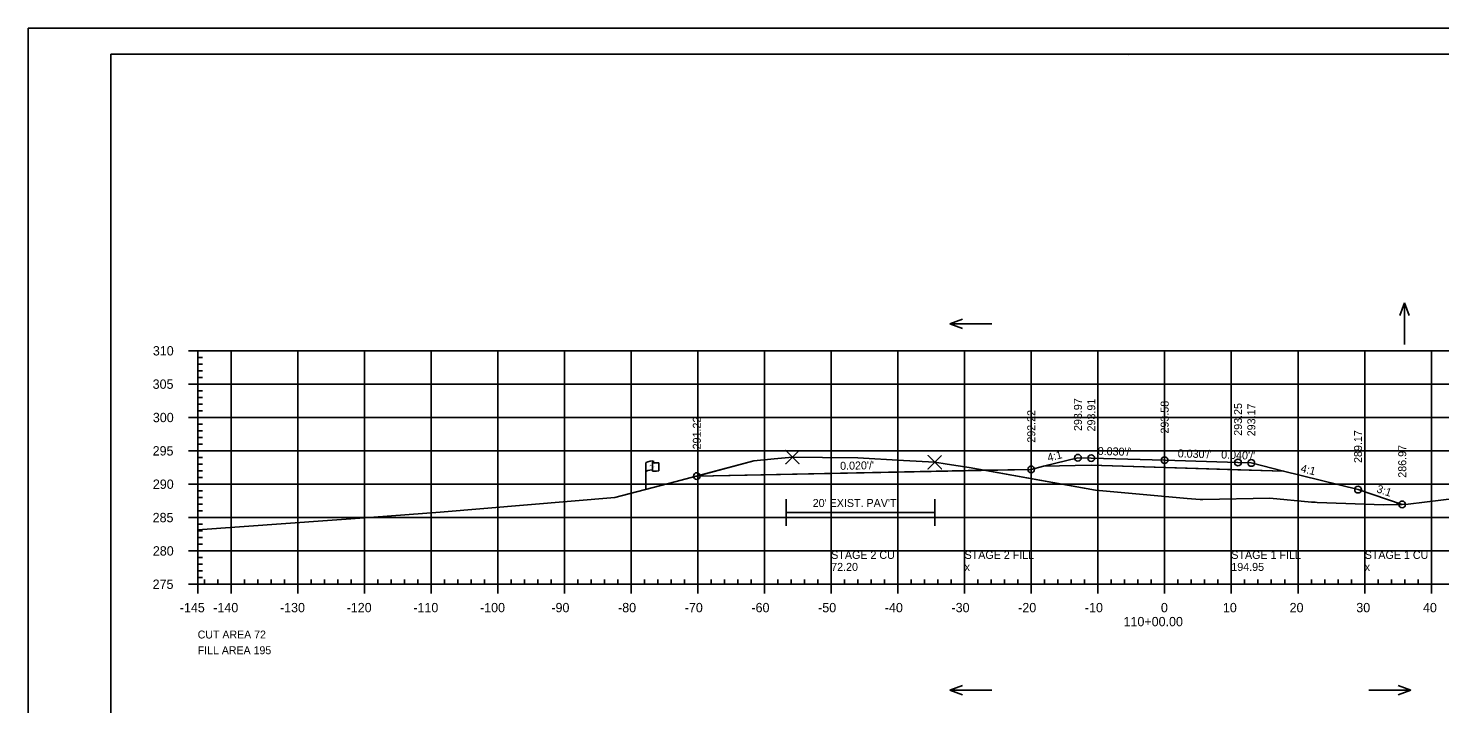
# Model space of a CAD drawing. Extents: x 1370843 to 1371177, y 380307 to 382654.
# Drawn here: x 1370843.3 to 1371055, y 381059.5 to 381160.8 of the extents above; entities that cross this region are included whole.
import ezdxf

# ---------------------------------------------------------------- set-up
doc = ezdxf.new("R2010")
doc.units = 0
for name, color, linetype in [('R_Alt Surface', 7, 'Continuous'), ('R_Axis', 7, 'Continuous'), ('R_Axis Annot', 7, 'Continuous'), ('R_Border', 7, 'Continuous'), ('R_Border Notes', 7, 'Continuous'), ('R_Exist Surface', 7, 'Continuous'), ('R_Exist Surface Annot', 7, 'Continuous'), ('R_Fin Surface', 7, 'Continuous'), ('R_Fin Surface Annot', 7, 'Continuous'), ('R_Grid', 7, 'Continuous'), ('R_No Plot', 7, 'Continuous'), ('R_ROW', 7, 'Continuous'), ('R_Water Annot', 7, 'Continuous')]:
    doc.layers.add(name, color=color, linetype=linetype)

msp = doc.modelspace()

# ---------------------------------------------------------------- linework, layer by layer
at = {"layer": 'R_Alt Surface'}
msp.add_lwpolyline([(1370995.56, 381095.15), (1371002.71, 381095.29), (1371013.71, 381094.96), (1371024.71, 381094.63), (1371031.54, 381094.43)], dxfattribs=at)
at = {"layer": 'R_Axis'}
for p, q in [((1370867.31, 381112.46), (1370868.71, 381112.46)), ((1370868.71, 381077.46), (1370868.71, 381112.46)), ((1370868.71, 381111.46), (1370869.41, 381111.46)), ((1370868.71, 381110.46), (1370869.41, 381110.46)), ((1370868.71, 381109.46), (1370869.41, 381109.46)), ((1370868.71, 381108.46), (1370869.41, 381108.46)), ((1370867.31, 381107.46), (1370868.71, 381107.46)), ((1370868.71, 381106.46), (1370869.41, 381106.46)), ((1370868.71, 381105.46), (1370869.41, 381105.46)), ((1370868.71, 381104.46), (1370869.41, 381104.46)), ((1370867.31, 381102.46), (1370868.71, 381102.46)), ((1370868.71, 381103.46), (1370869.41, 381103.46)), ((1370868.71, 381101.46), (1370869.41, 381101.46)), ((1370868.71, 381100.46), (1370869.41, 381100.46)), ((1370867.31, 381097.46), (1370868.71, 381097.46)), ((1370868.71, 381099.46), (1370869.41, 381099.46)), ((1370868.71, 381098.46), (1370869.41, 381098.46)), ((1370868.71, 381096.46), (1370869.41, 381096.46)), ((1370868.71, 381095.46), (1370869.41, 381095.46)), ((1370868.71, 381094.46), (1370869.41, 381094.46)), ((1370868.71, 381093.46), (1370869.41, 381093.46)), ((1370867.31, 381092.46), (1370868.71, 381092.46)), ((1370868.71, 381091.46), (1370869.41, 381091.46)), ((1370868.71, 381090.46), (1370869.41, 381090.46)), ((1370868.71, 381089.46), (1370869.41, 381089.46)), ((1370867.31, 381087.46), (1370868.71, 381087.46)), ((1370868.71, 381088.46), (1370869.41, 381088.46)), ((1370868.71, 381086.46), (1370869.41, 381086.46)), ((1370868.71, 381085.46), (1370869.41, 381085.46)), ((1370868.71, 381084.46), (1370869.41, 381084.46)), ((1370868.71, 381083.46), (1370869.41, 381083.46)), ((1370867.31, 381082.46), (1370868.71, 381082.46)), ((1370868.71, 381081.46), (1370869.41, 381081.46)), ((1370868.71, 381080.46), (1370869.41, 381080.46)), ((1370868.71, 381079.46), (1370869.41, 381079.46)), ((1370868.71, 381078.46), (1370869.41, 381078.46)), ((1370867.31, 381077.46), (1370868.71, 381077.46)), ((1370868.71, 381077.46), (1370868.71, 381078.16)), ((1370868.71, 381077.46), (1371158.71, 381077.46)), ((1370868.71, 381076.06), (1370868.71, 381077.46)), ((1370869.71, 381077.46), (1370869.71, 381078.16)), ((1370871.71, 381077.46), (1370871.71, 381078.16)), ((1370873.71, 381076.06), (1370873.71, 381077.46)), ((1370875.71, 381077.46), (1370875.71, 381078.16)), ((1370877.71, 381077.46), (1370877.71, 381078.16)), ((1370879.71, 381077.46), (1370879.71, 381078.16)), ((1370881.71, 381077.46), (1370881.71, 381078.16)), ((1370883.71, 381076.06), (1370883.71, 381077.46)), ((1370885.71, 381077.46), (1370885.71, 381078.16)), ((1370887.71, 381077.46), (1370887.71, 381078.16)), ((1370889.71, 381077.46), (1370889.71, 381078.16)), ((1370891.71, 381077.46), (1370891.71, 381078.16)), ((1370893.71, 381076.06), (1370893.71, 381077.46)), ((1370895.71, 381077.46), (1370895.71, 381078.16)), ((1370897.71, 381077.46), (1370897.71, 381078.16)), ((1370899.71, 381077.46), (1370899.71, 381078.16)), ((1370901.71, 381077.46), (1370901.71, 381078.16)), ((1370903.71, 381076.06), (1370903.71, 381077.46)), ((1370905.71, 381077.46), (1370905.71, 381078.16)), ((1370907.71, 381077.46), (1370907.71, 381078.16)), ((1370909.71, 381077.46), (1370909.71, 381078.16)), ((1370911.71, 381077.46), (1370911.71, 381078.16)), ((1370913.71, 381076.06), (1370913.71, 381077.46)), ((1370915.71, 381077.46), (1370915.71, 381078.16)), ((1370917.71, 381077.46), (1370917.71, 381078.16)), ((1370919.71, 381077.46), (1370919.71, 381078.16)), ((1370921.71, 381077.46), (1370921.71, 381078.16)), ((1370923.71, 381076.06), (1370923.71, 381077.46)), ((1370925.71, 381077.46), (1370925.71, 381078.16)), ((1370927.71, 381077.46), (1370927.71, 381078.16)), ((1370929.71, 381077.46), (1370929.71, 381078.16)), ((1370931.71, 381077.46), (1370931.71, 381078.16)), ((1370933.71, 381076.06), (1370933.71, 381077.46)), ((1370935.71, 381077.46), (1370935.71, 381078.16)), ((1370937.71, 381077.46), (1370937.71, 381078.16)), ((1370939.71, 381077.46), (1370939.71, 381078.16)), ((1370941.71, 381077.46), (1370941.71, 381078.16)), ((1370943.71, 381076.06), (1370943.71, 381077.46)), ((1370945.71, 381077.46), (1370945.71, 381078.16)), ((1370947.71, 381077.46), (1370947.71, 381078.16)), ((1370949.71, 381077.46), (1370949.71, 381078.16)), ((1370951.71, 381077.46), (1370951.71, 381078.16)), ((1370953.71, 381076.06), (1370953.71, 381077.46)), ((1370955.71, 381077.46), (1370955.71, 381078.16)), ((1370957.71, 381077.46), (1370957.71, 381078.16)), ((1370959.71, 381077.46), (1370959.71, 381078.16)), ((1370961.71, 381077.46), (1370961.71, 381078.16)), ((1370963.71, 381076.06), (1370963.71, 381077.46)), ((1370965.71, 381077.46), (1370965.71, 381078.16)), ((1370967.71, 381077.46), (1370967.71, 381078.16)), ((1370969.71, 381077.46), (1370969.71, 381078.16)), ((1370971.71, 381077.46), (1370971.71, 381078.16)), ((1370973.71, 381076.06), (1370973.71, 381077.46)), ((1370975.71, 381077.46), (1370975.71, 381078.16)), ((1370977.71, 381077.46), (1370977.71, 381078.16)), ((1370979.71, 381077.46), (1370979.71, 381078.16)), ((1370981.71, 381077.46), (1370981.71, 381078.16)), ((1370983.71, 381076.06), (1370983.71, 381077.46)), ((1370985.71, 381077.46), (1370985.71, 381078.16)), ((1370987.71, 381077.46), (1370987.71, 381078.16)), ((1370989.71, 381077.46), (1370989.71, 381078.16)), ((1370991.71, 381077.46), (1370991.71, 381078.16)), ((1370993.71, 381076.06), (1370993.71, 381077.46)), ((1370995.71, 381077.46), (1370995.71, 381078.16)), ((1370997.71, 381077.46), (1370997.71, 381078.16)), ((1370999.71, 381077.46), (1370999.71, 381078.16)), ((1371001.71, 381077.46), (1371001.71, 381078.16)), ((1371003.71, 381076.06), (1371003.71, 381077.46)), ((1371005.71, 381077.46), (1371005.71, 381078.16)), ((1371007.71, 381077.46), (1371007.71, 381078.16)), ((1371009.71, 381077.46), (1371009.71, 381078.16)), ((1371011.71, 381077.46), (1371011.71, 381078.16)), ((1371013.71, 381076.06), (1371013.71, 381077.46)), ((1371015.71, 381077.46), (1371015.71, 381078.16)), ((1371017.71, 381077.46), (1371017.71, 381078.16)), ((1371019.71, 381077.46), (1371019.71, 381078.16)), ((1371021.71, 381077.46), (1371021.71, 381078.16)), ((1371023.71, 381076.06), (1371023.71, 381077.46)), ((1371025.71, 381077.46), (1371025.71, 381078.16)), ((1371027.71, 381077.46), (1371027.71, 381078.16)), ((1371029.71, 381077.46), (1371029.71, 381078.16)), ((1371031.71, 381077.46), (1371031.71, 381078.16)), ((1371033.71, 381076.06), (1371033.71, 381077.46)), ((1371035.71, 381077.46), (1371035.71, 381078.16)), ((1371037.71, 381077.46), (1371037.71, 381078.16)), ((1371039.71, 381077.46), (1371039.71, 381078.16)), ((1371041.71, 381077.46), (1371041.71, 381078.16)), ((1371043.71, 381076.06), (1371043.71, 381077.46)), ((1371045.71, 381077.46), (1371045.71, 381078.16)), ((1371047.71, 381077.46), (1371047.71, 381078.16)), ((1371049.71, 381077.46), (1371049.71, 381078.16)), ((1371051.71, 381077.46), (1371051.71, 381078.16)), ((1371053.71, 381076.06), (1371053.71, 381077.46))]:
    msp.add_line(p, q, dxfattribs=at)
at = {"layer": 'R_Border'}
for p, q in [((1370855.71, 381156.92), (1371171.89, 381156.92)), ((1370855.71, 380951.46), (1370855.71, 381156.92)), ((1371008.23, 381156.66), (1371008.23, 381156.66)), ((1371008.23, 381156.66), (1371008.23, 381156.66))]:
    msp.add_line(p, q, dxfattribs=at)
at = {"layer": 'R_Exist Surface'}
msp.add_line((1370895.13, 381087.54), (1370868.71, 381085.61), dxfattribs=at)
msp.add_lwpolyline([(1370895.13, 381087.54), (1370905.06, 381088.27), (1370931.25, 381090.46), (1370940.28, 381092.81), (1370952.12, 381095.95), (1370955.16, 381096.25), (1370957.9, 381096.53), (1370962.4, 381096.48), (1370967.72, 381096.43), (1370974.57, 381096.03), (1370979.23, 381095.76), (1370981.12, 381095.47), (1370984.41, 381094.94), (1370997.74, 381092.58), (1371003.34, 381091.58), (1371017.09, 381090.34), (1371019.03, 381090.17), (1371019.44, 381090.19), (1371029.51, 381090.35), (1371035.71, 381089.78), (1371035.92, 381089.79), (1371036.29, 381089.76), (1371036.59, 381089.74), (1371046.57, 381089.36), (1371050.23, 381089.45), (1371062.5, 381090.97)], dxfattribs=at)
at = {"layer": 'R_Exist Surface Annot'}
for p, q in [((1370956.94, 381086.24), (1370956.94, 381090.24)), ((1370979.23, 381086.24), (1370979.23, 381090.24)), ((1370956.94, 381088.24), (1370979.23, 381088.24))]:
    msp.add_line(p, q, dxfattribs=at)
at = {"layer": 'R_Fin Surface'}
msp.add_lwpolyline([(1370943.56, 381093.68), (1370983.71, 381094.48), (1370993.71, 381094.68), (1370995.56, 381095.15), (1371000.71, 381096.43), (1371002.71, 381096.37), (1371013.71, 381096.05), (1371024.71, 381095.72), (1371026.71, 381095.64), (1371031.54, 381094.43), (1371042.71, 381091.64), (1371049.34, 381089.43)], dxfattribs=at)
at = {"layer": 'R_Grid'}
for p, q in [((1370868.71, 381112.46), (1371158.71, 381112.46)), ((1370868.71, 381077.46), (1370868.71, 381112.46)), ((1370873.71, 381077.46), (1370873.71, 381112.46)), ((1370883.71, 381077.46), (1370883.71, 381112.46)), ((1370893.71, 381077.46), (1370893.71, 381112.46)), ((1370903.71, 381077.46), (1370903.71, 381112.46)), ((1370913.71, 381077.46), (1370913.71, 381112.46)), ((1370923.71, 381077.46), (1370923.71, 381112.46)), ((1370933.71, 381077.46), (1370933.71, 381112.46)), ((1370943.71, 381077.46), (1370943.71, 381112.46)), ((1370953.71, 381077.46), (1370953.71, 381112.46)), ((1370963.71, 381077.46), (1370963.71, 381112.46)), ((1370973.71, 381077.46), (1370973.71, 381112.46)), ((1370983.71, 381077.46), (1370983.71, 381112.46)), ((1370993.71, 381077.46), (1370993.71, 381112.46)), ((1371003.71, 381077.46), (1371003.71, 381112.46)), ((1371013.71, 381077.46), (1371013.71, 381112.46)), ((1371023.71, 381077.46), (1371023.71, 381112.46)), ((1371033.71, 381077.46), (1371033.71, 381112.46)), ((1371043.71, 381077.46), (1371043.71, 381112.46)), ((1371053.71, 381077.46), (1371053.71, 381112.46)), ((1370868.71, 381107.46), (1371158.71, 381107.46)), ((1370868.71, 381102.46), (1371158.71, 381102.46)), ((1370868.71, 381097.46), (1371158.71, 381097.46)), ((1370868.71, 381092.46), (1371158.71, 381092.46)), ((1370868.71, 381087.46), (1371158.71, 381087.46)), ((1370868.71, 381082.46), (1371158.71, 381082.46)), ((1370868.71, 381077.46), (1371158.71, 381077.46))]:
    msp.add_line(p, q, dxfattribs=at)
at = {"layer": 'R_No Plot'}
msp.add_line((1370843.31, 381160.82), (1371176.64, 381160.82), dxfattribs=at)
for points in [[(1370843.3, 381160.82), (1371176.64, 381160.82), (1371176.64, 380947.48), (1370843.3, 380947.48)], [(1371089.63, 381156.92), (1371089.63, 381147.04), (1371125.36, 381147.04), (1371125.36, 381144.12), (1371148.56, 381144.12), (1371148.56, 381119.79), (1371171.89, 381119.79), (1371171.89, 380951.46), (1370855.71, 380951.46), (1370855.71, 381156.92)], [(1370943.56, 381093.68), (1370952.12, 381095.95), (1370955.16, 381096.25), (1370957.9, 381096.53), (1370962.4, 381096.48), (1370967.72, 381096.43), (1370974.57, 381096.03), (1370979.23, 381095.76), (1370981.12, 381095.47), (1370984.41, 381094.94), (1370986.64, 381094.54)], [(1370986.64, 381094.54), (1371003.34, 381091.58), (1371017.09, 381090.34), (1371019.03, 381090.17), (1371019.44, 381090.19), (1371029.51, 381090.35), (1371035.71, 381089.78), (1371036.29, 381089.76), (1371036.59, 381089.74), (1371046.57, 381089.36), (1371049.34, 381089.43), (1371042.71, 381091.64), (1371031.54, 381094.43), (1371002.71, 381095.29), (1370995.56, 381095.15), (1370993.71, 381094.68)]]:
    msp.add_lwpolyline(points, close=True, dxfattribs=at)
for points in [[(1370957.9, 381096.53), (1370956.9, 381097.53), (1370957.9, 381096.53), (1370956.9, 381095.53), (1370957.9, 381096.53), (1370958.9, 381095.53), (1370957.9, 381096.53), (1370958.9, 381097.53)], [(1370979.23, 381095.76), (1370978.23, 381096.76), (1370979.23, 381095.76), (1370978.23, 381094.76), (1370979.23, 381095.76), (1370980.23, 381094.76), (1370979.23, 381095.76), (1370980.23, 381096.76)]]:
    msp.add_lwpolyline(points, dxfattribs=at)
for centre in [(1371000.71, 381096.43), (1371002.71, 381096.37), (1371013.71, 381096.05), (1371024.71, 381095.72), (1371026.71, 381095.64), (1370943.56, 381093.68), (1370993.71, 381094.68), (1371042.71, 381091.64), (1371049.34, 381089.43)]:
    msp.add_circle(centre, 0.5, dxfattribs=at)
at = {"layer": 'R_ROW'}
for p, q in [((1370935.91, 381091.67), (1370935.91, 381095.63)), ((1370936.91, 381095.72), (1370936.91, 381095.71)), ((1370936.91, 381095.71), (1370936.91, 381094.48)), ((1370937.07, 381095.88), (1370937.07, 381095.64)), ((1370937.84, 381095.68), (1370937.84, 381094.44))]:
    msp.add_line(p, q, dxfattribs=at)
for centre, radius, start, end in [((1370936.98, 381095.72), 0.078, 88.6458, 274.2828), ((1370937, 381095.88), 0.0783, 263.0712, 93.9564), ((1370936.98, 381094.48), 0.0783, 180, 273.9564)]:
    msp.add_arc(centre, radius, start, end, dxfattribs=at)
for centre, major_axis, ratio, start_param, end_param in [((1370937.49, 381095.67), (-1.58, -0.04), 0.19887, 5.030368, 6.283185), ((1370938.2, 381095.78), (-1.23, -0.13), 0.052933, 0.159456, 1.268315), ((1370937.49, 381094.35), (-1.58, -0.04), 0.19887, 5.083035, 6.194897), ((1370938.2, 381094.54), (-1.23, -0.13), 0.052933, 0.159456, 1.268315)]:
    msp.add_ellipse(centre, major_axis=major_axis, ratio=ratio, start_param=start_param, end_param=end_param, dxfattribs=at)
at = {"layer": 'R_Water Annot'}
for p, q in [((1371049.66, 381119.66), (1371048.96, 381117.74)), ((1371049.66, 381113.38), (1371049.66, 381119.66)), ((1371049.66, 381119.66), (1371050.36, 381117.74)), ((1370981.5, 381116.52), (1370983.42, 381117.22)), ((1370987.78, 381116.52), (1370981.5, 381116.52)), ((1370981.5, 381116.52), (1370983.42, 381115.82)), ((1370981.5, 381061.6), (1370983.42, 381062.3)), ((1370987.78, 381061.6), (1370981.5, 381061.6)), ((1370981.5, 381061.6), (1370983.42, 381060.9)), ((1371044.35, 381061.6), (1371050.63, 381061.6)), ((1371050.63, 381061.6), (1371048.71, 381062.3)), ((1371050.63, 381061.6), (1371048.71, 381060.9))]:
    msp.add_line(p, q, dxfattribs=at)

# ---------------------------------------------------------------- texts
at = {"layer": 'R_Axis Annot'}
for s, p in [('310', (1370861.99, 381111.76)), ('305', (1370861.96, 381106.76)), ('300', (1370861.99, 381101.76)), ('295', (1370861.96, 381096.76)), ('290', (1370861.99, 381091.76)), ('285', (1370861.96, 381086.76)), ('280', (1370861.99, 381081.76)), ('275', (1370861.96, 381076.76)), ('-145', (1370866.03, 381073.26)), ('-140', (1370871.05, 381073.26)), ('-130', (1370881.05, 381073.26)), ('-120', (1370891.05, 381073.26)), ('-110', (1370901.05, 381073.26)), ('-100', (1370911.05, 381073.26)), ('-90', (1370921.75, 381073.26)), ('-80', (1370931.75, 381073.26)), ('-70', (1370941.75, 381073.26)), ('-60', (1370951.75, 381073.26)), ('-50', (1370961.75, 381073.26)), ('-40', (1370971.75, 381073.26)), ('-30', (1370981.75, 381073.26)), ('-20', (1370991.75, 381073.26)), ('-10', (1371001.75, 381073.26)), ('0', (1371013.15, 381073.26)), ('10', (1371022.45, 381073.26)), ('20', (1371032.45, 381073.26)), ('30', (1371042.45, 381073.26)), ('40', (1371052.45, 381073.26)), ('110+00.00', (1371007.55, 381071.16))]:
    msp.add_text(s, height=1.4, dxfattribs=at).set_placement(p)
at = {"layer": 'R_Border Notes'}
for s, p in [('CUT AREA 72', (1370868.71, 381069.33)), ('FILL AREA 195', (1370868.71, 381066.97))]:
    msp.add_text(s, height=1.1875, dxfattribs=at).set_placement(p)
at = {"layer": 'R_Exist Surface Annot'}
msp.add_text("20' EXIST. PAV'T", height=1.2, dxfattribs=at).set_placement((1370960.94, 381089.04))
at = {"layer": 'R_Fin Surface Annot'}
for s, rotation, p in [('293.97', 90, (1371001.31, 381100.43)), ('293.91', 90, (1371003.31, 381100.37)), ('293.58', 90, (1371014.31, 381100.05)), ('293.25', 90, (1371025.31, 381099.72)), ('293.17', 90, (1371027.31, 381099.64)), ('291.22', 90, (1370944.16, 381097.68)), ('292.22', 90, (1370994.31, 381098.68)), ('289.17', 90, (1371043.31, 381095.64)), ('4:1', 14.0362, (1370996.28, 381095.84)), ("0.030'/'", 358.288, (1371003.66, 381096.85)), ("0.030'/'", 358.288, (1371015.66, 381096.49)), ("0.040'/'", 357.7094, (1371022.17, 381096.32)), ('286.97', 90, (1371049.94, 381093.43)), ("0.020'/'", 1.1458, (1370965.06, 381094.61)), ('4:1', 345.9638, (1371034.02, 381094.32)), ('3:1', 341.5651, (1371045.39, 381091.27))]:
    msp.add_text(s, height=1.2, rotation=rotation, dxfattribs=at).set_placement(p)
at = {"layer": 'R_No Plot'}
for s, p in [('STAGE 2 CUT', (1370963.71, 381081.26)), ('72.20', (1370963.71, 381079.46)), ('STAGE 2 FILL', (1370983.71, 381081.26)), ('STAGE 1 FILL', (1371023.71, 381081.26)), ('194.95', (1371023.71, 381079.46)), ('STAGE 1 CUT', (1371043.71, 381081.26)), ('x', (1370983.71, 381079.46)), ('x', (1371043.71, 381079.46))]:
    msp.add_text(s, height=1.2, dxfattribs=at).set_placement(p)
at = {"layer": 'R_ROW'}
for s, height, rotation, p in [('R ', 0.2, 9.9884, (1370936.43, 381095.13)), (' O', 0.2, 9.9884, (1370936.58, 381095.17)), ('DWB 11-9-07', 0.001, 90, (1370937.07, 381095.64)), ('W', 0.2, 351.1788, (1370936.91, 381095)), ('DWB 11-9-07', 0.001, 5.0717, (1370937.83, 381094.44)), ('DWB 11-9-07', 0.001, 90, (1370935.91, 381091.68))]:
    msp.add_text(s, height=height, rotation=rotation, dxfattribs=at).set_placement(p)

doc.saveas('drawing.dxf')
